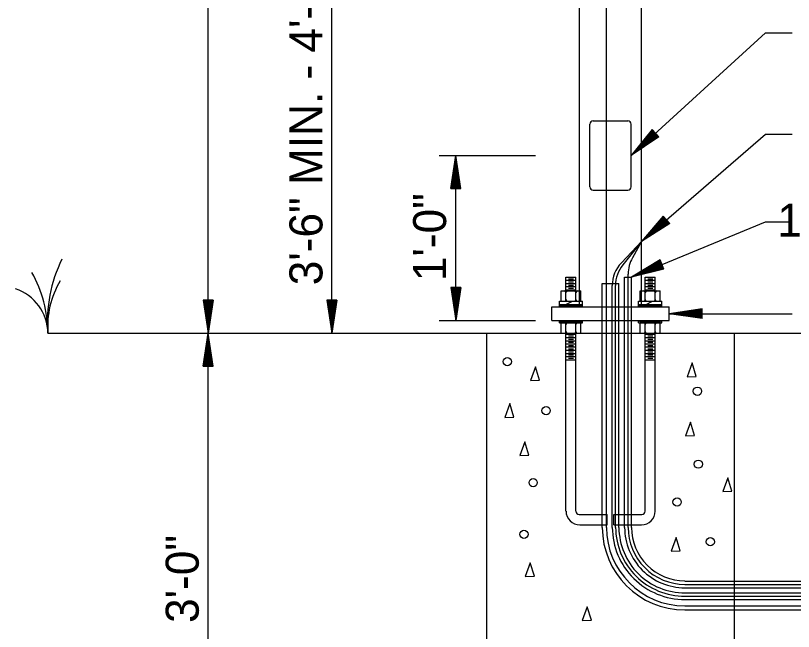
# Model space of a CAD drawing. Extents: x 418532 to 420296, y -565948 to -565286.
# Drawn here: x 418892.3 to 418998.3, y -565472.5 to -565388.6 of the extents above; entities that cross this region are included whole.
import ezdxf

# ---------------------------------------------------------------- set-up
doc = ezdxf.new("R2010")
doc.units = 0
doc.layers.add('R_Draft', color=7, linetype='Continuous')

msp = doc.modelspace()

# ---------------------------------------------------------------- linework, layer by layer
at = {"layer": 'R_Draft'}
for p, q in [((418918.52, -565431.83), (418918.52, -565293.23)), ((418969.15, -565428.23), (418969.15, -565337.55)), ((418977.59, -565428.23), (418977.59, -565337.55)), ((418935.4, -565431.83), (418935.4, -565341.83)), ((418972.81, -565458.28), (418972.81, -565359.33)), ((418976.18, -565407.61), (418994.49, -565390.91)), ((418994.49, -565390.91), (418998.1, -565390.91)), ((418971.01, -565402.88), (418975.73, -565402.88)), ((418970.56, -565411.88), (418970.56, -565403.33)), ((418976.18, -565411.88), (418976.18, -565403.33)), ((418979.05, -565404.07), (418976.18, -565407.61)), ((418979.12, -565404.16), (418976.74, -565407.1)), ((418979.88, -565404.99), (418976.74, -565407.1)), ((418979.2, -565404.24), (418977.31, -565406.58)), ((418979.81, -565404.9), (418977.31, -565406.58)), ((418977.59, -565419.35), (418994.49, -565404.72)), ((418979.28, -565404.32), (418977.86, -565406.07)), ((418979.73, -565404.82), (418977.86, -565406.07)), ((418979.35, -565404.41), (418978.42, -565405.56)), ((418979.65, -565404.73), (418978.42, -565405.56)), ((418979.43, -565404.49), (418978.98, -565405.05)), ((418979.57, -565404.65), (418978.98, -565405.05)), ((418979.96, -565405.07), (418979.05, -565404.07)), ((418994.49, -565404.72), (418998.1, -565404.72)), ((418979.96, -565405.07), (418976.18, -565407.61)), ((418950.02, -565407.61), (418963.13, -565407.61)), ((418951.6, -565412.11), (418952.27, -565407.61)), ((418952.27, -565430.11), (418952.27, -565407.61)), ((418952.95, -565412.11), (418952.27, -565407.61)), ((418951.71, -565412.11), (418952.27, -565408.36)), ((418951.83, -565412.11), (418952.27, -565409.13)), ((418952.84, -565412.11), (418952.27, -565408.36)), ((418952.72, -565412.11), (418952.27, -565409.13)), ((418951.94, -565412.11), (418952.27, -565409.88)), ((418952.61, -565412.11), (418952.27, -565409.88)), ((418952.06, -565412.11), (418952.27, -565410.64)), ((418952.17, -565412.11), (418952.27, -565411.39)), ((418952.49, -565412.11), (418952.27, -565410.64)), ((418952.38, -565412.11), (418952.27, -565411.39)), ((418951.6, -565412.11), (418952.95, -565412.11)), ((418971.01, -565412.33), (418975.73, -565412.33)), ((418976.22, -565424.18), (418994.49, -565416.64)), ((418980.53, -565415.87), (418977.59, -565419.35)), ((418980.6, -565415.96), (418978.15, -565418.85)), ((418980.68, -565416.04), (418978.73, -565418.34)), ((418981.27, -565416.72), (418978.73, -565418.34)), ((418980.75, -565416.13), (418979.3, -565417.85)), ((418981.19, -565416.63), (418979.3, -565417.85)), ((418980.83, -565416.22), (418979.87, -565417.34)), ((418981.12, -565416.55), (418979.87, -565417.34)), ((418980.9, -565416.3), (418980.44, -565416.85)), ((418981.04, -565416.46), (418980.44, -565416.85)), ((418981.42, -565416.89), (418980.53, -565415.87)), ((418994.49, -565416.64), (418998.1, -565416.64)), ((418981.42, -565416.89), (418977.59, -565419.35)), ((418981.34, -565416.8), (418978.15, -565418.85)), ((418977.59, -565419.35), (418974.84, -565422.22)), ((418977.59, -565419.35), (418975.04, -565422.5)), ((418977.59, -565419.35), (418976.34, -565421.55)), ((418980.12, -565421.84), (418976.22, -565424.18)), ((418980.16, -565421.95), (418976.91, -565423.9)), ((418980.64, -565423.09), (418980.12, -565421.84)), ((418980.59, -565422.99), (418976.91, -565423.9)), ((418980.21, -565422.05), (418977.63, -565423.6)), ((418980.55, -565422.88), (418977.63, -565423.6)), ((418980.25, -565422.16), (418978.32, -565423.32)), ((418980.51, -565422.78), (418978.32, -565423.32)), ((418980.29, -565422.26), (418979.03, -565423.02)), ((418980.46, -565422.67), (418979.03, -565423.02)), ((418980.34, -565422.37), (418979.72, -565422.74)), ((418980.42, -565422.56), (418979.72, -565422.74)), ((418975.75, -565458.28), (418975.75, -565423.77)), ((418980.64, -565423.09), (418976.22, -565424.18)), ((418967.29, -565424.18), (418968.64, -565424.18)), ((418967.29, -565426.06), (418967.29, -565424.18)), ((418967.29, -565424.62), (418968.64, -565424.62)), ((418967.29, -565425.05), (418968.64, -565425.05)), ((418967.63, -565424.41), (418968.31, -565424.41)), ((418967.63, -565424.84), (418968.31, -565424.84)), ((418968.64, -565426.06), (418968.64, -565424.18)), ((418972.24, -565458.28), (418972.24, -565425.05)), ((418972.24, -565425.05), (418974.49, -565425.05)), ((418974.49, -565458.28), (418974.49, -565425.05)), ((418975.28, -565458.28), (418975.28, -565424.18)), ((418975.28, -565424.18), (418976.22, -565424.18)), ((418976.22, -565458.28), (418976.22, -565424.18)), ((418978.09, -565424.18), (418979.44, -565424.18)), ((418978.09, -565426.06), (418978.09, -565424.18)), ((418978.09, -565424.62), (418979.44, -565424.62)), ((418978.09, -565425.05), (418979.44, -565425.05)), ((418978.43, -565424.41), (418979.11, -565424.41)), ((418978.43, -565424.84), (418979.11, -565424.84)), ((418979.44, -565426.06), (418979.44, -565424.18)), ((418951.6, -565425.61), (418952.27, -565430.11)), ((418952.95, -565425.61), (418951.6, -565425.61)), ((418951.71, -565425.61), (418952.27, -565429.35)), ((418951.83, -565425.61), (418952.27, -565428.58)), ((418951.94, -565425.61), (418952.27, -565427.83)), ((418952.05, -565425.61), (418952.27, -565427.07)), ((418952.17, -565425.61), (418952.27, -565426.32)), ((418952.95, -565425.61), (418952.27, -565430.11)), ((418952.49, -565425.61), (418952.27, -565427.07)), ((418952.72, -565425.61), (418952.27, -565428.58)), ((418952.84, -565425.61), (418952.27, -565429.35)), ((418952.61, -565425.61), (418952.27, -565427.83)), ((418952.38, -565425.61), (418952.27, -565426.32)), ((418966.62, -565427.48), (418966.62, -565426.06)), ((418966.62, -565426.06), (418969.32, -565426.06)), ((418967.29, -565425.48), (418968.64, -565425.48)), ((418967.29, -565425.91), (418968.64, -565425.91)), ((418967.29, -565427.48), (418967.29, -565426.06)), ((418967.63, -565425.27), (418968.31, -565425.27)), ((418967.63, -565425.71), (418968.31, -565425.71)), ((418968.64, -565427.48), (418968.64, -565426.06)), ((418969.32, -565427.48), (418969.32, -565426.06)), ((418973.59, -565458.28), (418973.59, -565425.33)), ((418974.04, -565458.28), (418974.04, -565425.33)), ((418977.42, -565427.48), (418977.42, -565426.06)), ((418977.42, -565426.06), (418980.12, -565426.06)), ((418978.09, -565425.48), (418979.44, -565425.48)), ((418978.09, -565425.91), (418979.44, -565425.91)), ((418978.09, -565427.48), (418978.09, -565426.06)), ((418978.43, -565425.27), (418979.11, -565425.27)), ((418978.43, -565425.71), (418979.11, -565425.71)), ((418979.44, -565427.48), (418979.44, -565426.06)), ((418980.12, -565427.48), (418980.12, -565426.06)), ((418917.85, -565427.33), (418918.52, -565431.83)), ((418919.2, -565427.33), (418917.85, -565427.33)), ((418917.96, -565427.33), (418918.52, -565431.08)), ((418918.08, -565427.33), (418918.52, -565430.3)), ((418918.19, -565427.33), (418918.52, -565429.55)), ((418918.3, -565427.33), (418918.52, -565428.79)), ((418918.42, -565427.33), (418918.52, -565428.04)), ((418919.2, -565427.33), (418918.52, -565431.83)), ((418918.74, -565427.33), (418918.52, -565428.79)), ((418918.97, -565427.33), (418918.52, -565430.3)), ((418919.09, -565427.33), (418918.52, -565431.08)), ((418918.86, -565427.33), (418918.52, -565429.55)), ((418918.63, -565427.33), (418918.52, -565428.04)), ((418934.72, -565427.33), (418935.4, -565431.83)), ((418936.07, -565427.33), (418934.72, -565427.33)), ((418934.84, -565427.33), (418935.4, -565431.08)), ((418934.95, -565427.33), (418935.4, -565430.3)), ((418935.06, -565427.33), (418935.4, -565429.55)), ((418935.18, -565427.33), (418935.4, -565428.79)), ((418935.29, -565427.33), (418935.4, -565428.04)), ((418936.07, -565427.33), (418935.4, -565431.83)), ((418935.62, -565427.33), (418935.4, -565428.79)), ((418935.85, -565427.33), (418935.4, -565430.3)), ((418935.96, -565427.33), (418935.4, -565431.08)), ((418935.73, -565427.33), (418935.4, -565429.55)), ((418935.51, -565427.33), (418935.4, -565428.04)), ((418965.38, -565430.11), (418965.38, -565428.23)), ((418965.38, -565428.23), (418981.36, -565428.23)), ((418966.39, -565428.23), (418966.39, -565427.48)), ((418966.39, -565427.48), (418969.54, -565427.48)), ((418966.39, -565427.93), (418969.54, -565427.93)), ((418966.39, -565428.09), (418966.55, -565427.93)), ((418966.41, -565428.23), (418966.71, -565427.93)), ((418966.57, -565428.23), (418966.87, -565427.93)), ((418966.73, -565428.23), (418967.03, -565427.93)), ((418966.89, -565428.23), (418967.19, -565427.93)), ((418967.05, -565428.23), (418967.29, -565427.98)), ((418967.2, -565428.23), (418967.29, -565428.14)), ((418967.29, -565427.93), (418968.08, -565427.49)), ((418967.29, -565428.16), (418967.52, -565427.93)), ((418967.29, -565428), (418967.37, -565427.93)), ((418967.38, -565428.23), (418967.68, -565427.93)), ((418967.54, -565428.23), (418967.84, -565427.93)), ((418967.7, -565428.23), (418968, -565427.93)), ((418967.86, -565428.23), (418968.16, -565427.93)), ((418968.02, -565428.23), (418968.32, -565427.93)), ((418968.18, -565428.23), (418968.48, -565427.93)), ((418968.34, -565428.23), (418968.64, -565427.93)), ((418968.5, -565428.23), (418968.64, -565428.08)), ((418968.64, -565428.12), (418968.83, -565427.93)), ((418968.64, -565427.96), (418968.67, -565427.93)), ((418968.69, -565428.23), (418968.99, -565427.93)), ((418968.85, -565428.23), (418969.15, -565427.93)), ((418969.01, -565428.23), (418969.15, -565428.09)), ((418969.15, -565428.22), (418969.43, -565427.93)), ((418969.15, -565428.06), (418969.28, -565427.93)), ((418969.29, -565428.23), (418969.54, -565427.98)), ((418969.45, -565428.23), (418969.54, -565428.14)), ((418969.54, -565428.23), (418969.54, -565427.48)), ((418977.19, -565428.23), (418977.19, -565427.48)), ((418977.19, -565427.48), (418980.34, -565427.48)), ((418977.19, -565427.93), (418980.34, -565427.93)), ((418977.23, -565428.23), (418977.53, -565427.93)), ((418977.25, -565428.05), (418977.37, -565427.93)), ((418977.39, -565428.23), (418977.59, -565428.03)), ((418977.54, -565428.23), (418977.59, -565428.19)), ((418977.59, -565428.14), (418977.79, -565427.93)), ((418977.59, -565427.98), (418977.64, -565427.93)), ((418977.65, -565428.23), (418977.95, -565427.93)), ((418977.81, -565428.23), (418978.09, -565427.95)), ((418977.97, -565428.23), (418978.09, -565428.11)), ((418978.09, -565428.15), (418978.31, -565427.93)), ((418978.09, -565427.99), (418978.16, -565427.93)), ((418978.17, -565428.23), (418978.47, -565427.93)), ((418978.23, -565427.93), (418978.97, -565427.49)), ((418978.33, -565428.23), (418978.63, -565427.93)), ((418978.49, -565428.23), (418978.79, -565427.93)), ((418978.65, -565428.23), (418978.95, -565427.93)), ((418978.81, -565428.23), (418979.11, -565427.93)), ((418978.97, -565428.23), (418979.27, -565427.93)), ((418979.13, -565428.23), (418979.43, -565427.93)), ((418979.29, -565428.23), (418979.44, -565428.07)), ((418979.44, -565428.1), (418979.61, -565427.93)), ((418979.44, -565427.94), (418979.45, -565427.93)), ((418979.47, -565428.23), (418979.77, -565427.93)), ((418979.63, -565428.23), (418979.93, -565427.93)), ((418979.79, -565428.23), (418980.09, -565427.93)), ((418979.95, -565428.23), (418980.25, -565427.93)), ((418980.11, -565428.23), (418980.29, -565428.05)), ((418980.27, -565428.23), (418980.33, -565428.17)), ((418980.34, -565428.23), (418980.34, -565427.48)), ((418981.36, -565430.11), (418981.36, -565428.23)), ((418985.86, -565428.49), (418981.36, -565429.17)), ((418981.36, -565429.17), (418998.1, -565429.17)), ((418985.86, -565429.84), (418981.36, -565429.17)), ((418985.86, -565428.61), (418982.11, -565429.17)), ((418985.86, -565429.73), (418982.11, -565429.17)), ((418985.86, -565428.72), (418982.88, -565429.17)), ((418985.86, -565429.62), (418982.88, -565429.17)), ((418985.86, -565428.83), (418983.63, -565429.17)), ((418985.86, -565429.5), (418983.63, -565429.17)), ((418985.86, -565428.95), (418984.39, -565429.17)), ((418985.86, -565429.39), (418984.39, -565429.17)), ((418985.86, -565429.06), (418985.14, -565429.17)), ((418985.86, -565429.27), (418985.14, -565429.17)), ((418985.86, -565429.84), (418985.86, -565428.49)), ((418950.02, -565430.11), (418963.13, -565430.11)), ((418965.38, -565430.11), (418981.36, -565430.11)), ((418966.39, -565430.41), (418966.39, -565430.11)), ((418966.39, -565430.26), (418966.54, -565430.11)), ((418966.39, -565430.41), (418969.54, -565430.41)), ((418966.4, -565430.41), (418966.7, -565430.11)), ((418966.56, -565430.41), (418966.86, -565430.11)), ((418966.62, -565431.83), (418966.62, -565430.41)), ((418966.72, -565430.41), (418967.02, -565430.11)), ((418966.88, -565430.41), (418967.18, -565430.11)), ((418967.04, -565430.41), (418967.29, -565430.15)), ((418967.2, -565430.41), (418967.29, -565430.31)), ((418967.29, -565430.34), (418967.53, -565430.11)), ((418967.29, -565430.18), (418967.37, -565430.11)), ((418967.29, -565431.83), (418967.29, -565430.41)), ((418967.38, -565430.41), (418967.68, -565430.11)), ((418967.54, -565430.41), (418967.84, -565430.11)), ((418967.7, -565430.41), (418968, -565430.11)), ((418967.86, -565430.41), (418968.16, -565430.11)), ((418968.02, -565430.41), (418968.32, -565430.11)), ((418968.18, -565430.41), (418968.48, -565430.11)), ((418968.34, -565430.41), (418968.64, -565430.11)), ((418968.5, -565430.41), (418968.64, -565430.26)), ((418968.64, -565430.41), (418968.94, -565430.11)), ((418968.64, -565430.25), (418968.78, -565430.11)), ((418968.64, -565431.83), (418968.64, -565430.41)), ((418968.8, -565430.41), (418969.1, -565430.11)), ((418968.96, -565430.41), (418969.26, -565430.11)), ((418969.12, -565430.41), (418969.42, -565430.11)), ((418969.28, -565430.41), (418969.54, -565430.14)), ((418969.32, -565431.83), (418969.32, -565430.41)), ((418969.44, -565430.41), (418969.54, -565430.3)), ((418969.54, -565430.41), (418969.54, -565430.11)), ((418977.19, -565430.41), (418977.19, -565430.11)), ((418977.19, -565430.41), (418980.34, -565430.41)), ((418977.2, -565430.11), (418977.21, -565430.11)), ((418977.27, -565430.2), (418977.37, -565430.11)), ((418977.34, -565430.3), (418977.53, -565430.11)), ((418977.4, -565430.39), (418977.68, -565430.11)), ((418977.42, -565431.83), (418977.42, -565430.41)), ((418977.54, -565430.41), (418977.84, -565430.11)), ((418977.7, -565430.41), (418978, -565430.11)), ((418977.86, -565430.41), (418978.09, -565430.17)), ((418978.02, -565430.41), (418978.09, -565430.33)), ((418978.09, -565430.35), (418978.33, -565430.11)), ((418978.09, -565430.19), (418978.17, -565430.11)), ((418978.09, -565431.83), (418978.09, -565430.41)), ((418978.19, -565430.41), (418978.49, -565430.11)), ((418978.35, -565430.41), (418978.65, -565430.11)), ((418978.51, -565430.41), (418978.81, -565430.11)), ((418978.67, -565430.41), (418978.97, -565430.11)), ((418978.83, -565430.41), (418979.13, -565430.11)), ((418978.99, -565430.41), (418979.29, -565430.11)), ((418979.15, -565430.41), (418979.44, -565430.11)), ((418979.31, -565430.41), (418979.44, -565430.27)), ((418979.44, -565430.27), (418979.61, -565430.11)), ((418979.44, -565430.11), (418979.45, -565430.11)), ((418979.44, -565431.83), (418979.44, -565430.41)), ((418979.46, -565430.41), (418979.76, -565430.11)), ((418979.62, -565430.41), (418979.92, -565430.11)), ((418979.78, -565430.41), (418980.08, -565430.11)), ((418979.94, -565430.41), (418980.24, -565430.11)), ((418980.1, -565430.41), (418980.17, -565430.34)), ((418980.12, -565431.83), (418980.12, -565430.41)), ((418980.34, -565430.41), (418980.34, -565430.11)), ((418896.71, -565431.83), (419134.51, -565431.83)), ((418917.85, -565436.33), (418918.52, -565431.83)), ((418917.96, -565436.33), (418918.52, -565432.58)), ((418918.52, -565499.33), (418918.52, -565431.83)), ((418919.2, -565436.33), (418918.52, -565431.83)), ((418919.09, -565436.33), (418918.52, -565432.58)), ((418956.49, -565499.33), (418956.49, -565431.83)), ((418956.49, -565431.83), (418990.24, -565431.83)), ((418966.62, -565431.83), (418969.32, -565431.83)), ((418967.29, -565456.06), (418967.29, -565431.83)), ((418967.29, -565431.97), (418968.64, -565431.97)), ((418967.29, -565432.4), (418968.64, -565432.4)), ((418967.63, -565432.2), (418968.31, -565432.2)), ((418968.64, -565456.08), (418968.64, -565431.83)), ((418977.42, -565431.83), (418980.12, -565431.83)), ((418978.09, -565456.08), (418978.09, -565431.83)), ((418978.09, -565431.97), (418979.44, -565431.97)), ((418978.09, -565432.4), (418979.44, -565432.4)), ((418978.43, -565432.2), (418979.11, -565432.2)), ((418979.44, -565456.06), (418979.44, -565431.83)), ((418990.24, -565499.33), (418990.24, -565431.83)), ((418918.08, -565436.33), (418918.52, -565433.35)), ((418918.97, -565436.33), (418918.52, -565433.35)), ((418967.29, -565432.84), (418968.64, -565432.84)), ((418967.29, -565433.27), (418968.64, -565433.27)), ((418967.63, -565432.63), (418968.31, -565432.63)), ((418967.63, -565433.06), (418968.31, -565433.06)), ((418967.63, -565433.49), (418968.31, -565433.49)), ((418978.09, -565432.84), (418979.44, -565432.84)), ((418978.09, -565433.27), (418979.44, -565433.27)), ((418978.43, -565432.63), (418979.11, -565432.63)), ((418978.43, -565433.06), (418979.11, -565433.06)), ((418978.43, -565433.49), (418979.11, -565433.49)), ((418918.19, -565436.33), (418918.52, -565434.1)), ((418918.86, -565436.33), (418918.52, -565434.1)), ((418967.29, -565433.7), (418968.64, -565433.7)), ((418967.29, -565434.13), (418968.64, -565434.13)), ((418967.29, -565434.57), (418968.64, -565434.57)), ((418967.63, -565433.93), (418968.31, -565433.93)), ((418967.63, -565434.36), (418968.31, -565434.36)), ((418978.09, -565433.7), (418979.44, -565433.7)), ((418978.09, -565434.13), (418979.44, -565434.13)), ((418978.09, -565434.57), (418979.44, -565434.57)), ((418978.43, -565433.93), (418979.11, -565433.93)), ((418978.43, -565434.36), (418979.11, -565434.36)), ((418918.31, -565436.33), (418918.52, -565434.86)), ((418918.42, -565436.33), (418918.52, -565435.62)), ((418918.74, -565436.33), (418918.52, -565434.86)), ((418918.63, -565436.33), (418918.52, -565435.62)), ((418967.29, -565435), (418968.64, -565435)), ((418967.29, -565435.43), (418968.64, -565435.43)), ((418967.63, -565434.79), (418968.31, -565434.79)), ((418967.63, -565435.22), (418968.31, -565435.22)), ((418978.09, -565435), (418979.44, -565435)), ((418978.09, -565435.43), (418979.44, -565435.43)), ((418978.43, -565434.79), (418979.11, -565434.79)), ((418978.43, -565435.22), (418979.11, -565435.22)), ((418917.85, -565436.33), (418919.2, -565436.33)), ((418969.09, -565456.53), (418972.92, -565456.53)), ((418972.92, -565457.93), (418972.92, -565456.53)), ((418973.82, -565457.93), (418973.82, -565456.53)), ((418973.82, -565456.53), (418977.64, -565456.53)), ((418969.17, -565457.93), (418972.92, -565457.93)), ((418973.82, -565457.93), (418977.57, -565457.93)), ((418983.49, -565465.58), (419094.8, -565465.58)), ((418983.49, -565466.05), (419093.69, -565466.05)), ((418983.49, -565466.51), (419094.8, -565466.51)), ((418983.49, -565467.19), (419094.8, -565467.19)), ((418983.49, -565467.64), (419101.04, -565467.64)), ((418983.49, -565468.09), (419097.77, -565468.09)), ((418983.49, -565468.97), (419094.8, -565468.97)), ((418983.49, -565469.53), (419094.8, -565469.53))]:
    msp.add_line(p, q, dxfattribs=at)
for points in [[(418963.15, -565436.39), (418962.46, -565438.26), (418963.7, -565438.21), (418963.15, -565436.39)], [(418984.49, -565435.88), (418983.81, -565437.75), (418985.04, -565437.7), (418984.49, -565435.88)], [(418959.63, -565441.42), (418958.95, -565443.29), (418960.18, -565443.24), (418959.63, -565441.42)], [(418984.26, -565443.94), (418983.58, -565445.8), (418984.82, -565445.75), (418984.26, -565443.94)], [(418961.67, -565446.64), (418960.99, -565448.5), (418962.23, -565448.45), (418961.67, -565446.64)], [(418989.33, -565451.51), (418988.65, -565453.38), (418989.88, -565453.33), (418989.33, -565451.51)], [(418982.29, -565459.65), (418981.61, -565461.52), (418982.84, -565461.47), (418982.29, -565459.65)], [(418962.43, -565463.11), (418961.75, -565464.98), (418962.98, -565464.93), (418962.43, -565463.11)], [(418970.19, -565469.11), (418969.51, -565470.98), (418970.75, -565470.93), (418970.19, -565469.11)]]:
    msp.add_lwpolyline(points, dxfattribs=at)
for centre in [(418959.3, -565435.7), (418985.2, -565439.73), (418964.58, -565442.37), (418985.32, -565449.66), (418962.82, -565452.18), (418982.43, -565454.82), (418961.57, -565459.22), (418986.96, -565460.23)]:
    msp.add_circle(centre, 0.562, dxfattribs=at)
for centre, radius, start, end in [((418971.01, -565403.33), 0.45, 90, 180), ((418975.73, -565403.33), 0.45, 360, 90), ((418971.01, -565411.88), 0.45, 180, 270), ((418975.73, -565411.88), 0.45, 270, 0), ((418915.59, -565430.17), 18.95, 153.6036, 185.017), ((418980.25, -565423.77), 4.5, 150.4069, 180), ((418978.09, -565425.33), 4.5, 136.323, 180), ((418978.54, -565425.33), 4.5, 141.118, 180), ((418879.5, -565431.95), 17.21, 0.407, 29.2294), ((418908.65, -565430.85), 11.98, 149.1449, 184.6717), ((418890.19, -565431.94), 6.52, 1.0116, 71.214), ((418967.07, -565426.28), 0.225, 0, 90), ((418967.52, -565426.28), 0.225, 90, 180), ((418968.42, -565426.28), 0.225, 0, 90), ((418968.87, -565426.28), 0.225, 90, 180), ((418977.87, -565426.28), 0.225, 0, 90), ((418978.32, -565426.28), 0.225, 90, 180), ((418979.22, -565426.28), 0.225, 0, 90), ((418979.67, -565426.28), 0.225, 90, 180), ((418967.07, -565427.25), 0.225, 270, 0), ((418967.52, -565427.25), 0.225, 180, 270), ((418968.42, -565427.25), 0.225, 270, 0), ((418968.87, -565427.25), 0.225, 180, 270), ((418977.87, -565427.25), 0.225, 270, 0), ((418978.32, -565427.25), 0.225, 180, 270), ((418979.22, -565427.25), 0.225, 270, 0), ((418979.67, -565427.25), 0.225, 180, 270), ((418967.07, -565430.63), 0.225, 0, 90), ((418967.52, -565430.63), 0.225, 90, 180), ((418968.42, -565430.63), 0.225, 0, 90), ((418968.87, -565430.63), 0.225, 90, 180), ((418977.87, -565430.63), 0.225, 0, 90), ((418978.32, -565430.63), 0.225, 90, 180), ((418979.22, -565430.63), 0.225, 0, 90), ((418979.67, -565430.63), 0.225, 90, 180), ((418967.07, -565431.6), 0.225, 270, 0), ((418967.52, -565431.6), 0.225, 180, 270), ((418968.42, -565431.6), 0.225, 270, 0), ((418968.87, -565431.6), 0.225, 180, 270), ((418977.87, -565431.6), 0.225, 270, 0), ((418978.32, -565431.6), 0.225, 180, 270), ((418979.22, -565431.6), 0.225, 270, 0), ((418979.67, -565431.6), 0.225, 180, 270), ((418969.17, -565456.06), 1.87, 180, 270), ((418969.09, -565456.08), 0.45, 180, 270), ((418977.57, -565456.06), 1.87, 270, 0), ((418977.64, -565456.08), 0.45, 270, 0), ((418983.49, -565458.28), 11.25, 180, 270), ((418983.49, -565458.28), 10.69, 180, 270), ((418983.45, -565458.24), 9.85, 180.3, 270.3), ((418983.45, -565458.24), 9.4, 180.3, 270.3), ((418983.45, -565458.24), 8.95, 180.3, 270.3), ((418983.5, -565458.29), 8.22, 179.9347, 269.9347), ((418983.5, -565458.29), 7.75, 179.9263, 269.9263), ((418983.5, -565458.29), 7.28, 179.9263, 269.9263)]:
    msp.add_arc(centre, radius, start, end, dxfattribs=at)

# ---------------------------------------------------------------- texts
for s, p in [('3\'-6" MIN. - 4\'-0" MAX.', (418934.11, -565425.29)), ('1\'-0"', (418950.96, -565424.73)), ('3\'-0"', (418917.25, -565471.29))]:
    msp.add_text(s, height=4.5, rotation=90, dxfattribs=at).set_placement(p)
msp.add_text(' 1/2" NMC ', height=4.5, dxfattribs=at).set_placement((418994.42, -565418.68))

doc.saveas('drawing.dxf')
